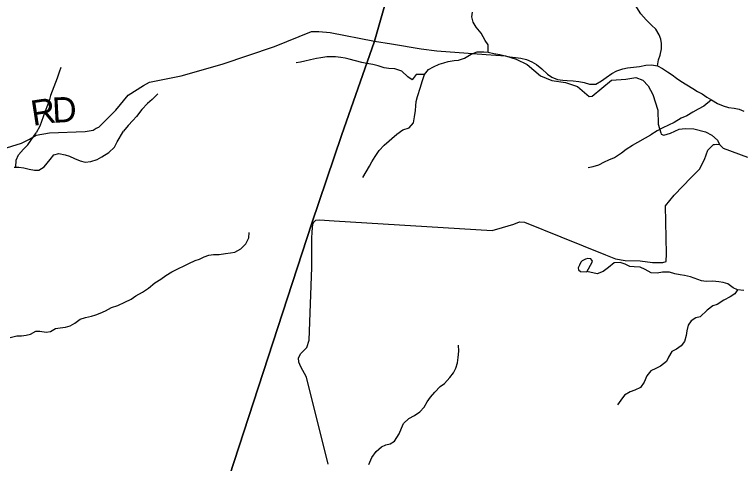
# Model space of a CAD drawing. Extents: x 1578669 to 1989827, y 208020 to 553079.
# Drawn here: x 1807123 to 1815751, y 406335 to 411669 of the extents above; entities that cross this region are included whole.
import ezdxf

# ---------------------------------------------------------------- set-up
doc = ezdxf.new("R2010")
doc.units = 0
for name, color, linetype in [('GM_X_Minor_Lake', 7, 'Continuous'), ('GM_X_Minor_River', 7, 'Continuous'), ('GM_X_Township', 7, 'Continuous'), ('GM_X_Township_Road', 7, 'Continuous'), ('GM_X_Township_Road_Text', 7, 'Continuous')]:
    doc.layers.add(name, color=color, linetype=linetype)

msp = doc.modelspace()

# ---------------------------------------------------------------- linework, layer by layer
at = {"layer": 'GM_X_Minor_Lake'}
for points in [[(1813914.4, 408611.8), (1813980, 408724.4), (1813984, 408736.5), (1813975.9, 408750.5), (1813961.8, 408764.4), (1813927.7, 408768.3), (1813901.7, 408760.1), (1813861.7, 408743.9), (1813845.8, 408727.8), (1813827.9, 408691.6), (1813814.1, 408659.4), (1813816.2, 408635.4), (1813842.3, 408615.5)], [(1813842.3, 408615.5), (1813914.4, 408611.8)]]:
    msp.add_lwpolyline(points, dxfattribs=at)
at = {"layer": 'GM_X_Minor_River'}
for points in [[(1814752.7, 411058), (1814768.1, 411130.3), (1814785.7, 411184.6), (1814801.1, 411260.9), (1814800.5, 411325), (1814794, 411377.1), (1814775.5, 411429), (1814734.9, 411492.8), (1814684.3, 411540.4), (1814619.6, 411603.9), (1814556.8, 411677.5), (1814508, 411753.2), (1814467.4, 411810.9), (1814424.7, 411884.7), (1814384, 411950.4), (1814345.4, 412010.2), (1814306.8, 412068), (1814272.1, 412129.8), (1814237.6, 412185.5), (1814205, 412237.3), (1814160.3, 412307.1), (1814121.6, 412374.8)], [(1812744.1, 411221), (1812743.4, 411307.2), (1812710.8, 411361), (1812659.9, 411448.7), (1812601.2, 411518.3), (1812566.6, 411576), (1812551.9, 411642), (1812557.5, 411696.2)], [(1811659.8, 410246.3), (1811733.5, 410299.1), (1811805.5, 410321.9), (1811857.1, 410380.5), (1811870.5, 410452.8), (1811881.9, 410527.1), (1811885.4, 410583.2), (1811889, 410635.4), (1811904.5, 410695.7), (1811939.7, 410804.2), (1811961.1, 410874.6), (1811988.5, 410955.1), (1812038.1, 411015.7), (1812095.9, 411048.3), (1812163.9, 411077), (1812219.8, 411095.6), (1812271.8, 411112.1), (1812341.9, 411120.9), (1812392, 411127.4), (1812462, 411148.1), (1812541.8, 411199), (1812615.7, 411225.7), (1812691.9, 411226.5), (1812744.1, 411221), (1812810.4, 411203.6), (1812882.7, 411192.2), (1812947, 411178.8), (1813003.3, 411167.4), (1813069.5, 411158), (1813133.8, 411148.6), (1813198.1, 411133.2), (1813262.4, 411107.7), (1813318.9, 411076.2), (1813383.5, 411022.7), (1813450.2, 410959.2), (1813500.7, 410923.6), (1813569.1, 410896.2), (1813631.3, 410886.8), (1813681.5, 410883.3), (1813751.7, 410880), (1813819.9, 410874.6), (1813882.2, 410859.2), (1813948.5, 410841.8), (1814020.7, 410840.5), (1814090.6, 410879.2), (1814144.4, 410919.8), (1814214.1, 410968.6), (1814272, 410999.2), (1814344, 411024), (1814398, 411034.5), (1814470.1, 411041.2), (1814540.2, 411051.9), (1814614.3, 411068.7), (1814682.4, 411071.3), (1814752.7, 411058), (1814815.1, 411026.5), (1814871.6, 410989), (1814928.1, 410953.5), (1814978.5, 410913.8), (1815031, 410878.3), (1815101.6, 410832.8), (1815174.1, 410789.4), (1815230.6, 410753.9), (1815283, 410726.3), (1815341.5, 410686.8), (1815395.9, 410655.3), (1815466.4, 410611.9), (1815534.9, 410582.5), (1815597.2, 410565), (1815663.4, 410555.6), (1815725.7, 410542.2), (1815778, 410520.7)], [(1811988.5, 410955.1), (1811888.2, 410956.1), (1811842.6, 410891.5), (1811790.2, 410929.1), (1811719.4, 410994.5), (1811637, 411021.8), (1811566.7, 411027.1), (1811508.5, 411036.6), (1811438.1, 411057.9), (1811375.8, 411073.4), (1811303.5, 411086.7), (1811243.3, 411100.1), (1811170.9, 411119.5), (1811096.5, 411138.8), (1811046.3, 411148.3), (1810996.1, 411157.8), (1810931.9, 411165.2), (1810881.7, 411166.8), (1810829.6, 411164.2), (1810757.5, 411155.5), (1810705.4, 411147), (1810635.4, 411128.3), (1810569.4, 411115.6), (1810517.3, 411103), (1810467.3, 411096.5)], [(1807672.4, 411041), (1807652.8, 410984.7), (1807627.4, 410912.3), (1807607.8, 410860), (1807590.2, 410809.7), (1807568.6, 410759.3), (1807551, 410705.1), (1807533.5, 410642.8), (1807515.9, 410590.5), (1807486.5, 410520), (1807461, 410451.6), (1807443.4, 410399.3), (1807421.8, 410341), (1807378.4, 410264.4)], [(1808822.2, 410725.6), (1808754.6, 410660.8), (1808702.9, 410610.2), (1808635.3, 410539.3), (1808569.8, 410458.5), (1808526.2, 410408), (1808470.5, 410349.3), (1808417, 410282.6)], [(1815395.9, 410655.3), (1815306.3, 410578.2), (1815236.4, 410545.5), (1815174.6, 410506.8), (1815100.8, 410466), (1815036.9, 410435.3), (1814953.1, 410386.4), (1814885.2, 410355.7), (1814817.3, 410323), (1814751.4, 410288.3), (1814673.7, 410237.4)], [(1807117.3, 409854.5), (1807175.4, 409854.8), (1807233.5, 409847.1), (1807295.7, 409829.4), (1807359.8, 409819.7), (1807411.9, 409820), (1807475.8, 409860.4), (1807547.5, 409945), (1807589.3, 410001.3), (1807647.4, 410015.7), (1807725.5, 410002), (1807775.7, 409986.3), (1807833.9, 409958.5), (1807900.1, 409928.8), (1807962.3, 409913.1), (1808028.3, 409921.5), (1808104.3, 409948), (1808160.3, 409976.3), (1808242.1, 410030.9), (1808307.9, 410093.4), (1808339.7, 410155.7), (1808417, 410282.6)], [(1807137.4, 409854.6), (1807141, 409936.8), (1807168.7, 410003.1), (1807228.5, 410067.5), (1807280.4, 410121.9), (1807378.4, 410264.4)], [(1811255.7, 409732.4), (1811297.5, 409800.8), (1811337.2, 409867.1), (1811363, 409917.4), (1811404.8, 409981.7), (1811450.5, 410054.1), (1811508.3, 410114.6), (1811659.8, 410246.3)], [(1813932.8, 409852.7), (1813990.9, 409863), (1814058.9, 409883.4), (1814124.8, 409919.8), (1814176.8, 409940.2), (1814242.7, 409970.6), (1814326.6, 410027.1), (1814384.5, 410069.5), (1814458.4, 410118), (1814673.7, 410237.4)], [(1807070.4, 407829.8), (1807150.4, 407850.2), (1807206.5, 407852.5), (1807260.5, 407858.8), (1807310.5, 407871.1), (1807374.5, 407907.5), (1807424.6, 407905.8), (1807496.7, 407896.2), (1807550.7, 407902.5), (1807610.7, 407936.9), (1807662.7, 407945.2), (1807728.8, 407955.5), (1807782.8, 407971.9), (1807836.7, 408002.2), (1807900.6, 408048.7), (1807964.6, 408067.1), (1808036.6, 408085.5), (1808088.6, 408101.8), (1808140.6, 408120.1), (1808202.6, 408148.5), (1808274.5, 408187), (1808350.5, 408213.5), (1808432.4, 408250), (1808506.4, 408288.5), (1808562.3, 408324.8), (1808642.2, 408371.4), (1808712.1, 408417.9), (1808787.9, 408480.4), (1808859.8, 408524.9), (1808919.7, 408569.3), (1808991.6, 408609.8), (1809067.5, 408652.3), (1809135.5, 408684.7), (1809191.4, 408711.1), (1809265.4, 408745.6), (1809317.4, 408763.9), (1809373.3, 408788.2), (1809429.3, 408808.6), (1809483.4, 408816.9), (1809551.4, 408819.3), (1809625.5, 408829.7), (1809685.6, 408836), (1809739.6, 408844.3), (1809809.5, 408884.8), (1809869.3, 408943.2), (1809903.1, 409013.6), (1809908.8, 409079.8)], [(1815777.9, 408389), (1815705.8, 408398.7), (1815653.6, 408420.4), (1815589.3, 408468.2), (1815533.2, 408484), (1815481.1, 408491.7), (1815411, 408499.4), (1815332.9, 408497), (1815276.8, 408502.7), (1815146.4, 408552.1), (1815076.2, 408567.8), (1815022.1, 408577.5), (1814961.9, 408587.2), (1814895.8, 408608.9), (1814815.7, 408608.5), (1814751.6, 408596.2), (1814677.5, 408599.8), (1814609.2, 408637.5), (1814547, 408665.3), (1814478.9, 408670.9), (1814426.8, 408676.6), (1814372.6, 408702.4), (1814310.5, 408722.2), (1814240.4, 408717.8), (1814174.5, 408663.3), (1814110.7, 408616.9), (1814038.7, 408588.4), (1813916.7, 408615.8)], [(1815705.8, 408398.7), (1815672, 408348.4), (1815616.1, 408314), (1815542.1, 408275.5), (1815462.3, 408225), (1815410.3, 408206.7), (1815342.4, 408154.2), (1815262.6, 408077.7), (1815210.6, 408063.4), (1815152.7, 408031), (1815116.9, 407976.7), (1815101.2, 407910.5), (1815095.4, 407854.3), (1815073.7, 407782), (1815035.9, 407731.7), (1814980, 407691.3), (1814924, 407667), (1814886.3, 407596.6), (1814860.5, 407546.4), (1814790.7, 407489.9), (1814736.7, 407461.6), (1814676.7, 407437.2), (1814626.9, 407376.8), (1814597.2, 407302.5), (1814551.5, 407238.1), (1814485.5, 407203.7), (1814429.5, 407185.4), (1814363.6, 407146.9), (1814317.8, 407086.6), (1814278, 407032.2)], [(1811327.2, 406323.2), (1811364.9, 406405.6), (1811414.6, 406478), (1811478.5, 406530.5), (1811530.4, 406554.8), (1811582.4, 406567.1), (1811634.3, 406601.5), (1811688, 406685.9), (1811715.8, 406752.2), (1811741.6, 406810.5), (1811803.4, 406868.9), (1811869.3, 406905.4), (1811933.2, 406949.8), (1811983, 407004.2), (1812018.8, 407066.5), (1812058.6, 407120.8), (1812110.4, 407181.2), (1812176.2, 407247.7), (1812228.1, 407286.1), (1812289.8, 407356.6), (1812333.6, 407412.9), (1812361.4, 407467.2), (1812379.2, 407531.4), (1812386.9, 407593.6), (1812394.6, 407667.8), (1812394.3, 407740)]]:
    msp.add_lwpolyline(points, dxfattribs=at)
at = {"layer": 'GM_X_Township'}
for points in [[(1794613.6, 432491), (1800877.7, 431987.5), (1805342.9, 431618.8), (1806251.4, 431555.7), (1812295.7, 431153.9), (1812748.1, 423763.1), (1812980.7, 420551.4), (1813182.7, 417646.4), (1813168.5, 417494.8), (1813100.6, 417317.5), (1811396.3, 411351.9), (1811003, 410233.1), (1810652.7, 409191.2), (1809037.4, 404232.9), (1808867.4, 403681), (1808758.2, 403152.3), (1808679.5, 402774.7), (1808603.5, 402343.9), (1807249.9, 395260.6), (1804835, 395343.7), (1793084.6, 395748)], [(1817084.3, 393898.6), (1817267.6, 394775.1), (1817352.8, 395143.3), (1807249.9, 395260.6), (1808603.5, 402343.9), (1808679.5, 402774.7), (1808758.2, 403152.3), (1808867.4, 403681), (1809037.4, 404232.9), (1810652.7, 409191.2), (1811003, 410233.1), (1811396.3, 411351.9), (1813100.6, 417317.5)]]:
    msp.add_lwpolyline(points, dxfattribs=at)
at = {"layer": 'GM_X_Township_Road'}
for points in [[(1806731.6, 409994.2), (1807204.9, 410140.9), (1807299, 410187.3), (1807381.1, 410236.1), (1807535.9, 410263.4), (1807962.1, 410278.6), (1808055.8, 410296.4), (1808091.2, 410317), (1808122.4, 410330), (1808326, 410531), (1808470.2, 410709.8), (1808653.8, 410824.3), (1808723.6, 410865.4), (1809099.9, 410938.8), (1809587.9, 411080.3), (1810210.3, 411287.1), (1810646.4, 411465.4), (1810735.6, 411467.8), (1810868.2, 411453.3), (1811396.3, 411351.9), (1811598, 411318.5)], [(1811598, 411318.5), (1811947.9, 411260.6), (1812133.4, 411238.8), (1812719, 411195.5), (1812950.4, 411176.2), (1813075.7, 411137.6), (1813205.9, 411075), (1813364.9, 410940), (1813500.2, 410885.5), (1813663.8, 410862.9), (1813803.5, 410814.7), (1813941.5, 410693.6), (1813980.6, 410700.2), (1814208.4, 410887), (1814377.1, 410901.5), (1814497.6, 410920.7), (1814579.5, 410887), (1814642.2, 410819.5), (1814700, 410718.3), (1814757.9, 410530.3), (1814763.5, 410364.1), (1814792.9, 410261.4), (1814798.5, 410245.5), (1814829.6, 410237.1), (1814909.8, 410258.8), (1815011.3, 410306.3), (1815083.2, 410315.4), (1815185.1, 410310.7), (1815322.5, 410276.7), (1815401.2, 410234.1), (1815466.1, 410173.9), (1815490.6, 410125.9)], [(1810846.2, 406324.9), (1810587.8, 407360), (1810519.1, 407483.4), (1810497.7, 407539.9), (1810494.3, 407590.1), (1810523, 407641.9), (1810592.1, 407711.3), (1810621.3, 407801.3), (1810651.5, 408662.5), (1810650.2, 409013.3), (1810655.2, 409084.7), (1810664, 409182.4), (1810675.3, 409202.5), (1810697.8, 409223.8), (1810741.7, 409228.8), (1810915.8, 409218.7), (1812790.5, 409104.5), (1812913.3, 409139.1), (1813048.2, 409177.5), (1813114.8, 409204.8), (1813177, 409201.9), (1813606.3, 409025.8), (1814135.5, 408812.2), (1814255.4, 408766.5), (1814369.5, 408745), (1814550.1, 408740.7), (1814694.3, 408720.7), (1814816.8, 408723.2), (1814857.1, 408734.7), (1814860.1, 408825), (1814849, 409395.3), (1814952.9, 409520.4), (1815154.1, 409732.6), (1815251.7, 409831.7), (1815311.3, 409945.4), (1815352.7, 410055.2), (1815419.6, 410123.1), (1815431.5, 410124.4), (1815452.7, 410128.4), (1815490.6, 410125.9), (1815534.5, 410079.7), (1815822.7, 409974.6)]]:
    msp.add_lwpolyline(points, dxfattribs=at)

# ---------------------------------------------------------------- texts
at = {"layer": 'GM_X_Township_Road_Text'}
for s, rotation, p in [('R', 8.8245, (1807342.2, 410344.5)), ('D', 2.92644, (1807577.6, 410381.4))]:
    msp.add_text(s, height=300, rotation=rotation, dxfattribs=at).set_placement(p)

doc.saveas('drawing.dxf')
